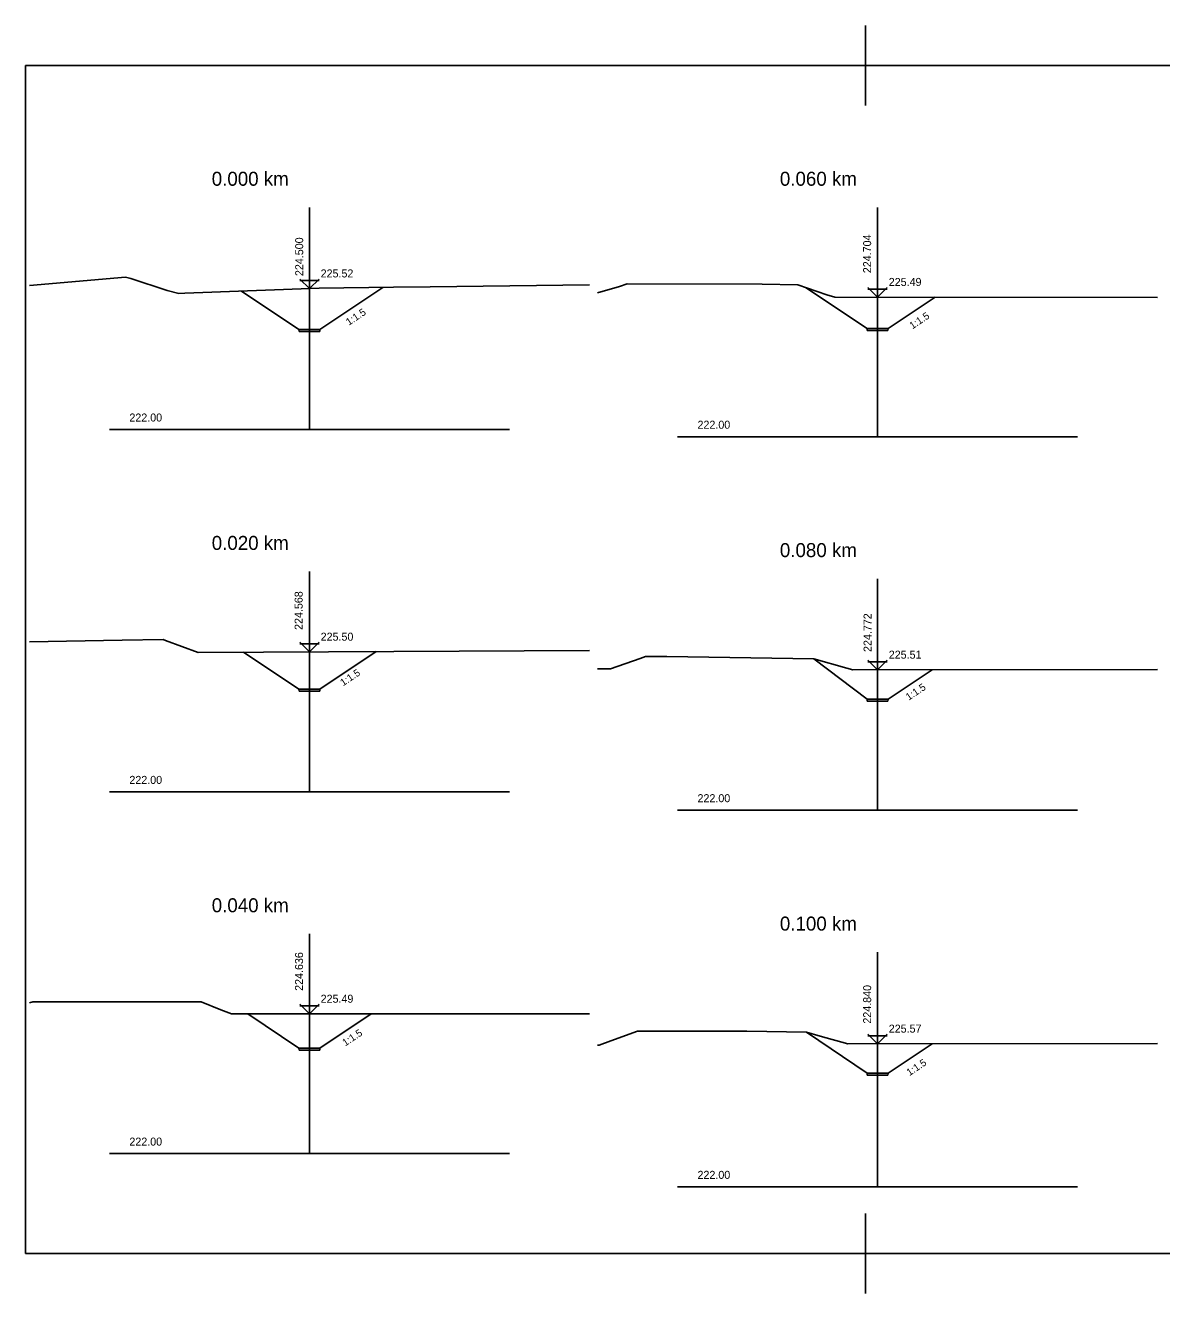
# Model space of a CAD drawing. Extents: x -495905 to -478420, y -1113297 to -1107716.
# Drawn here: x -493293.5 to -493009.5, y -1110271.4 to -1109954.4 of the extents above; entities that cross this region are included whole.
import ezdxf

# ---------------------------------------------------------------- set-up
doc = ezdxf.new("R2010")
doc.units = 0
for name, color, linetype in [('FORMATY', 7, 'Continuous'), ('legenda', 7, 'Continuous'), ('WORKING_LAYER', 7, 'Continuous')]:
    doc.layers.add(name, color=color, linetype=linetype)

msp = doc.modelspace()

# ---------------------------------------------------------------- linework, layer by layer
at = {"layer": 'FORMATY'}
for p, q in [((-493083.45, -1109954.44), (-493083.45, -1109974.44)), ((-493293.45, -1109964.44), (-493293.45, -1110261.44)), ((-493293.45, -1109964.44), (-492663.45, -1109964.44)), ((-493093.45, -1109964.44), (-493073.45, -1109964.44)), ((-493083.45, -1110251.44), (-493083.45, -1110271.44)), ((-493093.45, -1110261.44), (-493073.45, -1110261.44))]:
    msp.add_line(p, q, dxfattribs=at)
at = {"layer": 'legenda'}
msp.add_line((-492663.45, -1110261.44), (-493293.45, -1110261.44), dxfattribs=at)
at = {"layer": 'WORKING_LAYER'}
for p, q in [((-493222.45, -1110055.46), (-493222.45, -1109999.94)), ((-493080.45, -1110057.26), (-493080.45, -1109999.94)), ((-493292.45, -1110019.44), (-493268.45, -1110017.35)), ((-493268.45, -1110017.35), (-493267.08, -1110017.73)), ((-493267.08, -1110017.73), (-493257.98, -1110020.7)), ((-493222.45, -1110020.24), (-493224.85, -1110017.84)), ((-493224.85, -1110018.24), (-493220.05, -1110018.24)), ((-493222.45, -1110020.24), (-493220.05, -1110017.84)), ((-493201.42, -1110019.91), (-493192.26, -1110019.8)), ((-493192.26, -1110019.8), (-493152.45, -1110019.3)), ((-493150.45, -1110021.27), (-493144.95, -1110019.71)), ((-493144.95, -1110019.71), (-493143.03, -1110019.04)), ((-493143.03, -1110019.04), (-493109.32, -1110019.14)), ((-493109.32, -1110019.14), (-493100.37, -1110019.28)), ((-493100.37, -1110019.28), (-493093.12, -1110021.79)), ((-493257.98, -1110020.7), (-493255.07, -1110021.43)), ((-493255.07, -1110021.43), (-493253.6, -1110021.38)), ((-493253.6, -1110021.38), (-493220.05, -1110020.15)), ((-493239.45, -1110020.86), (-493225.06, -1110030.46)), ((-493225.06, -1110030.46), (-493239.45, -1110020.86)), ((-493220.05, -1110020.15), (-493201.42, -1110019.91)), ((-493219.84, -1110030.46), (-493204.08, -1110019.94)), ((-493219.84, -1110030.46), (-493204.08, -1110019.94)), ((-493098.48, -1110019.94), (-493083.06, -1110030.22)), ((-493083.06, -1110030.22), (-493098.48, -1110019.94)), ((-493093.12, -1110021.79), (-493091.09, -1110022.36)), ((-493091.09, -1110022.36), (-493010.45, -1110022.43)), ((-493080.45, -1110022.37), (-493082.85, -1110019.97)), ((-493082.85, -1110020.37), (-493078.05, -1110020.37)), ((-493080.45, -1110022.37), (-493078.05, -1110019.97)), ((-493077.84, -1110030.22), (-493066.09, -1110022.38)), ((-493077.84, -1110030.22), (-493066.09, -1110022.38)), ((-493225.06, -1110030.46), (-493225.05, -1110030.96)), ((-493224.95, -1110030.46), (-493225.05, -1110030.46)), ((-493225.05, -1110030.96), (-493224.95, -1110030.96)), ((-493222.45, -1110030.46), (-493224.95, -1110030.46)), ((-493224.95, -1110030.96), (-493222.45, -1110030.96)), ((-493222.45, -1110030.46), (-493219.95, -1110030.46)), ((-493222.45, -1110030.96), (-493219.95, -1110030.96)), ((-493222.45, -1110030.96), (-493222.45, -1110030.96)), ((-493219.95, -1110030.46), (-493219.85, -1110030.46)), ((-493219.95, -1110030.96), (-493219.85, -1110030.96)), ((-493219.85, -1110030.96), (-493219.84, -1110030.46)), ((-493083.06, -1110030.22), (-493083.05, -1110030.72)), ((-493082.95, -1110030.22), (-493083.05, -1110030.22)), ((-493083.05, -1110030.72), (-493082.95, -1110030.72)), ((-493080.45, -1110030.22), (-493082.95, -1110030.22)), ((-493082.95, -1110030.72), (-493080.45, -1110030.72)), ((-493080.45, -1110030.22), (-493077.95, -1110030.22)), ((-493080.45, -1110030.72), (-493077.95, -1110030.72)), ((-493080.45, -1110030.72), (-493080.45, -1110030.72)), ((-493077.95, -1110030.22), (-493077.85, -1110030.22)), ((-493077.95, -1110030.72), (-493077.85, -1110030.72)), ((-493077.85, -1110030.72), (-493077.84, -1110030.22)), ((-493272.45, -1110055.46), (-493172.45, -1110055.46)), ((-493130.45, -1110057.26), (-493030.45, -1110057.26)), ((-493222.45, -1110146.03), (-493222.45, -1110090.96)), ((-493080.45, -1110150.61), (-493080.45, -1110092.76)), ((-493292.45, -1110108.53), (-493269.26, -1110108.08)), ((-493269.26, -1110108.08), (-493258.99, -1110107.92)), ((-493258.99, -1110107.92), (-493258.39, -1110108.16)), ((-493258.39, -1110108.16), (-493250.24, -1110111.17)), ((-493222.45, -1110111.04), (-493224.85, -1110108.64)), ((-493222.45, -1110111.04), (-493220.05, -1110108.64)), ((-493250.24, -1110111.17), (-493152.45, -1110110.71)), ((-493238.9, -1110111.12), (-493225.06, -1110120.35)), ((-493225.06, -1110120.35), (-493238.9, -1110111.12)), ((-493224.85, -1110109.04), (-493220.05, -1110109.04)), ((-493219.84, -1110120.35), (-493205.76, -1110110.96)), ((-493219.84, -1110120.35), (-493205.76, -1110110.96)), ((-493147.24, -1110115.28), (-493139.81, -1110112.67)), ((-493139.81, -1110112.67), (-493138.49, -1110112.18)), ((-493138.49, -1110112.18), (-493133.09, -1110112.2)), ((-493133.09, -1110112.2), (-493096.41, -1110112.79)), ((-493096.41, -1110112.79), (-493088.13, -1110115.1)), ((-493096.41, -1110112.79), (-493083.06, -1110122.89)), ((-493083.06, -1110122.89), (-493096.41, -1110112.79)), ((-493080.45, -1110115.53), (-493082.85, -1110113.13)), ((-493082.85, -1110113.53), (-493078.05, -1110113.53)), ((-493080.45, -1110115.53), (-493078.05, -1110113.13)), ((-493150.45, -1110115.26), (-493147.24, -1110115.28)), ((-493088.13, -1110115.1), (-493086.62, -1110115.53)), ((-493086.62, -1110115.53), (-493010.45, -1110115.47)), ((-493077.84, -1110122.89), (-493066.79, -1110115.51)), ((-493077.84, -1110122.89), (-493066.79, -1110115.51)), ((-493225.06, -1110120.35), (-493225.05, -1110120.85)), ((-493224.95, -1110120.35), (-493225.05, -1110120.35)), ((-493225.05, -1110120.85), (-493224.95, -1110120.85)), ((-493222.45, -1110120.35), (-493224.95, -1110120.35)), ((-493224.95, -1110120.85), (-493222.45, -1110120.85)), ((-493222.45, -1110120.35), (-493219.95, -1110120.35)), ((-493222.45, -1110120.85), (-493219.95, -1110120.85)), ((-493222.45, -1110120.85), (-493222.45, -1110120.85)), ((-493219.95, -1110120.35), (-493219.85, -1110120.35)), ((-493219.95, -1110120.85), (-493219.85, -1110120.85)), ((-493219.85, -1110120.85), (-493219.84, -1110120.35)), ((-493083.06, -1110122.89), (-493083.05, -1110123.39)), ((-493082.95, -1110122.89), (-493083.05, -1110122.89)), ((-493083.05, -1110123.39), (-493082.95, -1110123.39)), ((-493080.45, -1110122.89), (-493082.95, -1110122.89)), ((-493082.95, -1110123.39), (-493080.45, -1110123.39)), ((-493080.45, -1110122.89), (-493077.95, -1110122.89)), ((-493080.45, -1110123.39), (-493077.95, -1110123.39)), ((-493080.45, -1110123.39), (-493080.45, -1110123.39)), ((-493077.95, -1110122.89), (-493077.85, -1110122.89)), ((-493077.95, -1110123.39), (-493077.85, -1110123.39)), ((-493077.85, -1110123.39), (-493077.84, -1110122.89)), ((-493272.45, -1110146.03), (-493172.45, -1110146.03)), ((-493130.45, -1110150.61), (-493030.45, -1110150.61)), ((-493222.45, -1110236.44), (-493222.45, -1110181.53)), ((-493080.45, -1110244.75), (-493080.45, -1110186.11)), ((-493292.45, -1110198.77), (-493291.58, -1110198.52)), ((-493291.58, -1110198.52), (-493286.87, -1110198.53)), ((-493286.87, -1110198.53), (-493249.47, -1110198.48)), ((-493249.47, -1110198.48), (-493244.57, -1110200.49)), ((-493244.57, -1110200.49), (-493241.93, -1110201.54)), ((-493222.45, -1110201.53), (-493224.85, -1110199.13)), ((-493224.85, -1110199.53), (-493220.05, -1110199.53)), ((-493222.45, -1110201.53), (-493220.05, -1110199.13)), ((-493241.93, -1110201.54), (-493152.45, -1110201.51)), ((-493237.86, -1110201.54), (-493225.06, -1110210.08)), ((-493225.06, -1110210.08), (-493237.86, -1110201.54)), ((-493219.84, -1110210.08), (-493207.02, -1110201.53)), ((-493219.84, -1110210.08), (-493207.02, -1110201.53)), ((-493147.12, -1110208.29), (-493140.46, -1110205.8)), ((-493140.46, -1110205.8), (-493113.15, -1110205.87)), ((-493113.15, -1110205.87), (-493098.19, -1110206.11)), ((-493098.19, -1110206.11), (-493094.81, -1110207.06)), ((-493098.19, -1110206.11), (-493083.06, -1110216.35)), ((-493083.06, -1110216.35), (-493098.19, -1110206.11)), ((-493080.45, -1110209), (-493082.85, -1110206.6)), ((-493080.45, -1110209), (-493078.05, -1110206.6)), ((-493225.06, -1110210.08), (-493225.05, -1110210.58)), ((-493224.95, -1110210.08), (-493225.05, -1110210.08)), ((-493222.45, -1110210.08), (-493224.95, -1110210.08)), ((-493222.45, -1110210.08), (-493219.95, -1110210.08)), ((-493219.95, -1110210.08), (-493219.85, -1110210.08)), ((-493219.85, -1110210.58), (-493219.84, -1110210.08)), ((-493150.45, -1110209.32), (-493150.06, -1110209.32)), ((-493150.06, -1110209.32), (-493147.12, -1110208.29)), ((-493094.81, -1110207.06), (-493087.9, -1110209.01)), ((-493087.9, -1110209.01), (-493010.45, -1110208.95)), ((-493082.85, -1110207), (-493078.05, -1110207)), ((-493077.84, -1110216.35), (-493066.82, -1110208.99)), ((-493077.84, -1110216.35), (-493066.82, -1110208.99)), ((-493225.05, -1110210.58), (-493224.95, -1110210.58)), ((-493224.95, -1110210.58), (-493222.45, -1110210.58)), ((-493222.45, -1110210.58), (-493219.95, -1110210.58)), ((-493222.45, -1110210.58), (-493222.45, -1110210.58)), ((-493219.95, -1110210.58), (-493219.85, -1110210.58)), ((-493083.06, -1110216.35), (-493083.05, -1110216.85)), ((-493082.95, -1110216.35), (-493083.05, -1110216.35)), ((-493080.45, -1110216.35), (-493082.95, -1110216.35)), ((-493080.45, -1110216.35), (-493077.95, -1110216.35)), ((-493077.95, -1110216.35), (-493077.85, -1110216.35)), ((-493077.85, -1110216.85), (-493077.84, -1110216.35)), ((-493083.05, -1110216.85), (-493082.95, -1110216.85)), ((-493082.95, -1110216.85), (-493080.45, -1110216.85)), ((-493080.45, -1110216.85), (-493077.95, -1110216.85)), ((-493080.45, -1110216.85), (-493080.45, -1110216.85)), ((-493077.95, -1110216.85), (-493077.85, -1110216.85)), ((-493272.45, -1110236.44), (-493172.45, -1110236.44)), ((-493130.45, -1110244.75), (-493030.45, -1110244.75))]:
    msp.add_line(p, q, dxfattribs=at)

# ---------------------------------------------------------------- texts
for s, height, p in [('    0.000 km', 3.5, (-493252.07, -1109994.53)), ('    0.060 km', 3.5, (-493110.07, -1109994.53)), ('225.52', 2, (-493219.65, -1110017.44)), ('225.49', 2, (-493077.65, -1110019.57)), ('222.00', 2, (-493267.45, -1110053.46)), ('222.00', 2, (-493125.45, -1110055.26)), ('    0.020 km', 3.5, (-493252.07, -1110085.55)), ('    0.080 km', 3.5, (-493110.07, -1110087.35)), ('225.50', 2, (-493219.65, -1110108.24)), ('225.51', 2, (-493077.65, -1110112.73)), ('222.00', 2, (-493267.45, -1110144.03)), ('222.00', 2, (-493125.45, -1110148.61)), ('    0.040 km', 3.5, (-493252.07, -1110176.12)), ('    0.100 km', 3.5, (-493110.07, -1110180.7)), ('225.49', 2, (-493219.65, -1110198.73)), ('225.57', 2, (-493077.65, -1110206.2)), ('222.00', 2, (-493267.45, -1110234.44)), ('222.00', 2, (-493125.45, -1110242.75))]:
    msp.add_text(s, height=height, dxfattribs=at).set_placement(p)
for s, height, rotation, p in [('224.704', 2, 90, (-493082.05, -1110016.38)), ('224.500', 2, 90, (-493224, -1110017.1)), ('1:1.5', 1.8, 33.7069, (-493212.59, -1110029.53)), ('1:1.5', 1.8, 33.7128, (-493071.74, -1110030.45)), ('224.568', 2, 90, (-493224.15, -1110105.55)), ('224.772', 2, 90, (-493081.95, -1110111.06)), ('1:1.5', 1.8, 33.7087, (-493214.02, -1110119.66)), ('1:1.5', 1.8, 33.7142, (-493072.66, -1110123.25)), ('224.636', 2, 90, (-493224.05, -1110195.76)), ('224.840', 2, 90, (-493082.05, -1110203.96)), ('1:1.5', 1.8, 33.7109, (-493213.49, -1110209.67)), ('1:1.5', 1.8, 33.7143, (-493072.48, -1110217.1))]:
    msp.add_text(s, height=height, rotation=rotation, dxfattribs=at).set_placement(p)

doc.saveas('drawing.dxf')
